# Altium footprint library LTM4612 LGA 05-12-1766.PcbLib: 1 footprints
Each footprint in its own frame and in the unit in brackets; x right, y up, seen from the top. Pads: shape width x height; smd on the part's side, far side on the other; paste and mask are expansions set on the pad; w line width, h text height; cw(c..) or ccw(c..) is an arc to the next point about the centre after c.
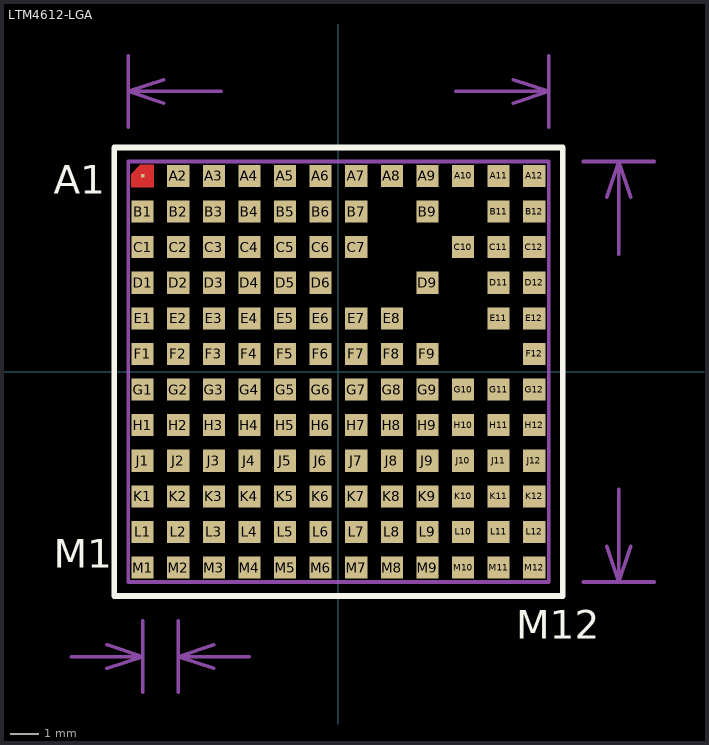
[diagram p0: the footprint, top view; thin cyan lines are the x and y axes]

## LTM4612-LGA [mil]
pads (133):
  rect 5x5 smd paste-3.5 mask-3: A1(-275,275)
  rect 31x31 smd paste-3.5 mask-3: A2(-225,275) A3(-175,275) A4(-125,275) A5(-75,275) A6(-25,275) A7(25,275) A8(75,275) A9(125,275) A10(175,275) A11(225,275) A12(275,275) B1(-275,225) B2(-225,225) B3(-175,225) B4(-125,225) B5(-75,225) B6(-25,225) B7(25,225) B9(125,225) B11(225,225) B12(275,225) C1(-275,175) C2(-225,175) C3(-175,175) C4(-125,175) C5(-75,175) C6(-25,175) C7(25,175) C10(175,175) C11(225,175) C12(275,175) D1(-275,125) D2(-225,125) D3(-175,125) D4(-125,125) D5(-75,125) D6(-25,125) D9(125,125) D11(225,125) D12(275,125) E1(-275,75) E2(-225,75) E3(-175,75) E4(-125,75) E5(-75,75) E6(-25,75) E7(25,75) E8(75,75) E11(225,75) E12(275,75) F1(-275,25) F2(-225,25) F3(-175,25) F4(-125,25) F5(-75,25) F6(-25,25) F7(25,25) F8(75,25) F9(125,25) F12(275,25) G1(-275,-25) G2(-225,-25) G3(-175,-25) G4(-125,-25) G5(-75,-25) G6(-25,-25) G7(25,-25) G8(75,-25) G9(125,-25) G10(175,-25) G11(225,-25) G12(275,-25) H1(-275,-75) H2(-225,-75) H3(-175,-75) H4(-125,-75) H5(-75,-75) H6(-25,-75) H7(25,-75) H8(75,-75) H9(125,-75) H10(175,-75) H11(225,-75) H12(275,-75) J1(-275,-125) J2(-225,-125) J3(-175,-125) J4(-125,-125) J5(-75,-125) J6(-25,-125) J7(25,-125) J8(75,-125) J9(125,-125) J10(175,-125) J11(225,-125) J12(275,-125) K1(-275,-175) K2(-225,-175) K3(-175,-175) K4(-125,-175) K5(-75,-175) K6(-25,-175) K7(25,-175) K8(75,-175) K9(125,-175) K10(175,-175) K11(225,-175) K12(275,-175) L1(-275,-225) L2(-225,-225) L3(-175,-225) L4(-125,-225) L5(-75,-225) L6(-25,-225) L7(25,-225) L8(75,-225) L9(125,-225) L10(175,-225) L11(225,-225) L12(275,-225) M1(-275,-275) M2(-225,-275) M3(-175,-275) M4(-125,-275) M5(-75,-275) M6(-25,-275) M7(25,-275) M8(75,-275) M9(125,-275) M10(175,-275) M11(225,-275) M12(275,-275)
TopLayer:
  region: -290.5,259.5 -259.5,259.5 -259.5,290.5 -277.5,290.5 -290.5,277.5
  lines w0.39: -290.5,259.5 -290.5,277.5 -277.5,290.5 -259.5,290.5 -259.5,259.5 -290.5,259.5
TopOverlay:
  lines w8: -314.96,-314.96 -314.96,314.96 314.96,314.96 314.96,-314.96 -314.96,-314.96
  text "M12" at 250,-375 h40
  text "A1" at -400,250 h40
  text "M1" at -400,-275 h40
Mechanical16:
  lines w5: -375,-400 -275,-400 ; -325,-416.67 -275,-400 ; -325,-383.33 -275,-400 ; -295.28,343.7 -295.28,443.7 ; -275,-450 -275,-350 ; -245.28,377.03 -295.28,393.7 ; -245.28,410.37 -295.28,393.7 ; -225,-450 -225,-350 ; -175,-416.67 -225,-400 ; -175,-383.33 -225,-400 ; -164.95,393.7 -295.28,393.7 ; -125,-400 -225,-400 ; 164.95,393.7 295.28,393.7 ; 245.28,377.03 295.28,393.7 ; 245.28,410.37 295.28,393.7 ; 295.28,343.7 295.28,443.7 ; 343.7,-295.28 443.7,-295.28 ; 343.7,295.28 443.7,295.28 ; 377.03,-245.28 393.7,-295.28 ; 377.03,245.28 393.7,295.28 ; 393.7,-164.95 393.7,-295.28 ; 393.7,164.95 393.7,295.28 ; 410.37,-245.28 393.7,-295.28 ; 410.37,245.28 393.7,295.28 ; -295.28,-295.28 295.28,-295.28 295.28,295.28 -295.28,295.28 -295.28,-295.28
  text "1.27 (mm)" at -450.77,-519.97 h50
  text "15 (mm)" at 423.69,-154.95 h50
  text "15 (mm)" at -154.95,363.71 h50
